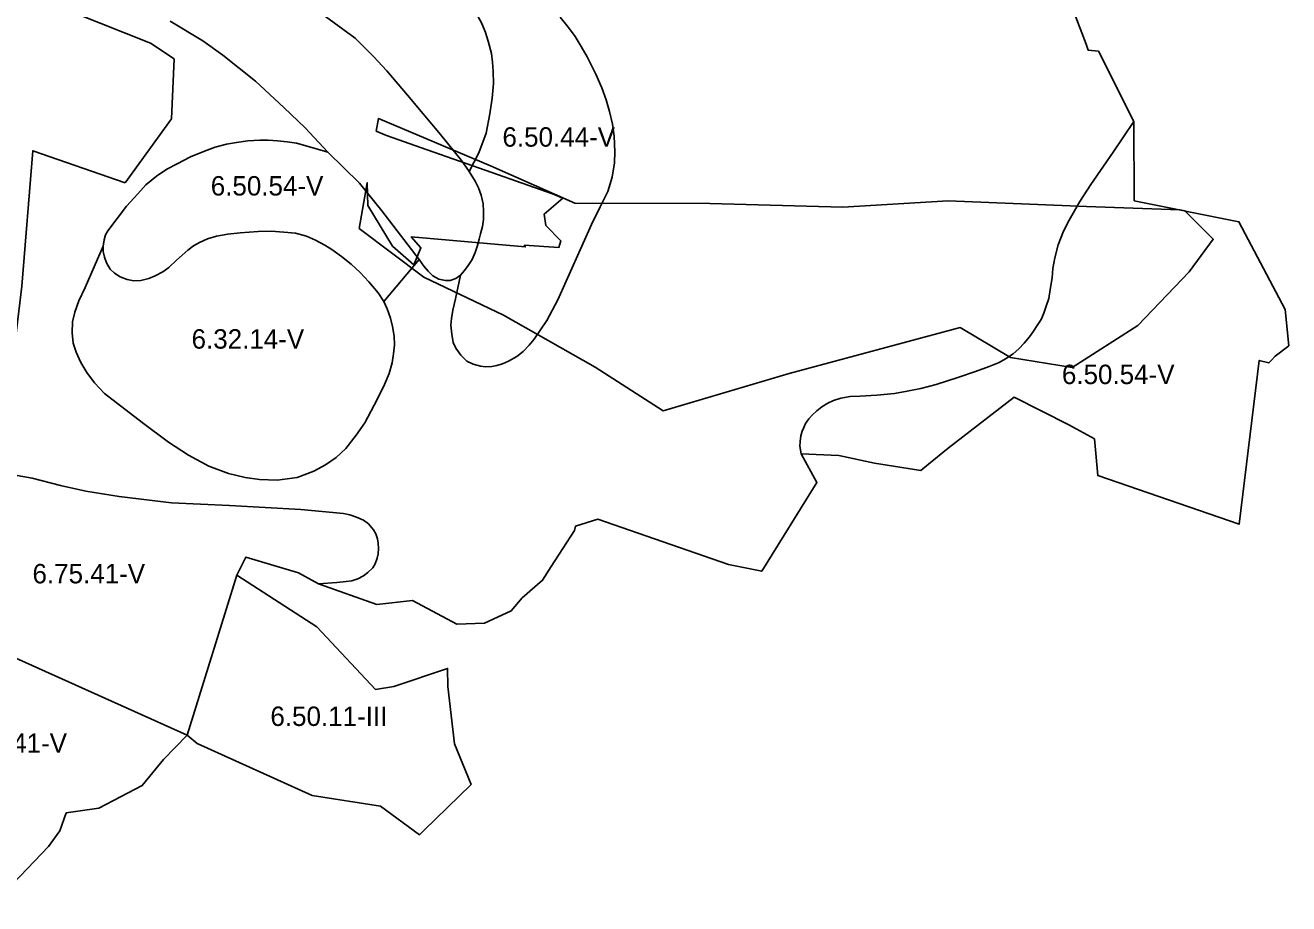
# Model space of a CAD drawing. Extents: x -555156 to -540209, y -1046851 to -1035695.
# Drawn here: x -543112 to -542461, y -1042405 to -1041952 of the extents above; entities that cross this region are included whole.
import ezdxf

# ---------------------------------------------------------------- set-up
doc = ezdxf.new("R2010")
doc.units = 0
for name, color, linetype in [('Vrstva 27', 7, 'Continuous'), ('Vrstva 28', 7, 'Continuous'), ('Vrstva 29', 7, 'Continuous')]:
    doc.layers.add(name, color=color, linetype=linetype)

msp = doc.modelspace()

# ---------------------------------------------------------------- linework, layer by layer
at = {"layer": 'Vrstva 28'}
for points in [[(-543225.96, -1041792.46), (-543222.64, -1041795.92), (-543215.38, -1041803.54), (-543208.99, -1041809.13), (-543200.39, -1041816.16), (-543189.37, -1041824.04), (-543175.69, -1041832.52), (-543154.37, -1041842.09), (-543111.98, -1041858.81), (-543067, -1041879.05), (-543042.63, -1041892.2), (-543014.86, -1041908.52), (-542980.74, -1041930.37), (-542941.96, -1041958.78), (-542932.46, -1041968.21), (-542925.68, -1041975.6), (-542915.02, -1041988.2), (-542897.95, -1042008.44), (-542887.17, -1042021.77), (-542883.23, -1042027.58)], [(-542581.52, -1041920.08), (-542565.67, -1041961.95), (-542564.48, -1041965.09), (-542559.18, -1041965.6), (-542541, -1042001.74)], [(-542883.23, -1042027.58), (-542878.31, -1042017.92), (-542874.5, -1042007.74), (-542872.68, -1041997.81), (-542871.35, -1041989.81), (-542870.74, -1041982.18), (-542870.86, -1041976), (-542871.23, -1041971.15), (-542871.85, -1041966.73), (-542873.43, -1041960.43), (-542874.88, -1041955.95), (-542876.82, -1041951.35), (-542879.6, -1041945.89), (-542882.75, -1041940.2), (-542885.9, -1041935.35), (-542892.58, -1041927.43)], [(-542956.03, -1042017.47), (-542967.69, -1042004.96), (-542978.71, -1041994.57), (-542993.33, -1041981), (-543010.07, -1041967.64), (-543020.46, -1041960.22), (-543037.2, -1041950.04)], [(-542836.49, -1041948.07), (-542832.13, -1041953.28), (-542828.62, -1041958.01), (-542825.59, -1041963.1), (-542822.44, -1041968.43), (-542818.01, -1041977.42), (-542814.99, -1041984.45), (-542812.81, -1041990.63), (-542810.99, -1041996.57), (-542809.54, -1042003.11), (-542808.69, -1042009.29), (-542808.33, -1042017.41), (-542808.45, -1042023.1), (-542809.66, -1042030.49), (-542811.84, -1042037.76), (-542815.83, -1042045.62), (-542820.28, -1042054.74), (-542837.66, -1042093.54), (-542843.2, -1042104.17), (-542849.74, -1042113.87), (-542852.3, -1042116.97), (-542855.55, -1042120.29), (-542858.8, -1042122.71), (-542863.02, -1042125.14), (-542866.07, -1042126.52), (-542869.11, -1042127.49), (-542871.67, -1042127.98), (-542874.65, -1042128.05), (-542877.42, -1042127.77), (-542881.22, -1042126.8), (-542884.41, -1042125.14), (-542887.59, -1042122.16), (-542890.22, -1042118.49), (-542891.47, -1042115.51), (-542892.23, -1042111.36), (-542892.64, -1042106.65), (-542892.43, -1042103.26), (-542891.6, -1042098.89), (-542890.36, -1042093.15), (-542887.69, -1042080.92)], [(-542712.28, -1042173.01), (-542712.98, -1042168.98), (-542712.91, -1042166.56), (-542712.57, -1042163.58), (-542711.88, -1042161.3), (-542711.04, -1042159.43), (-542710.08, -1042157.28), (-542708.42, -1042154.93), (-542706.48, -1042152.78), (-542704.26, -1042150.77), (-542701.7, -1042148.77), (-542698.66, -1042146.9), (-542695.61, -1042145.51), (-542691.88, -1042144.33), (-542687.1, -1042143.43), (-542681.98, -1042143.3), (-542673.4, -1042142.74), (-542664.33, -1042141.84), (-542657.83, -1042140.73), (-542650.63, -1042139.28), (-542642.81, -1042137.13), (-542631.67, -1042133.53), (-542622.52, -1042130.59), (-542615.46, -1042127.88), (-542610.41, -1042125.88), (-542607.15, -1042124.08), (-542603.21, -1042121.38), (-542600.23, -1042118.81), (-542597.53, -1042115.91), (-542594.76, -1042112.65), (-542592.76, -1042109.81), (-542590.75, -1042106.84), (-542588.74, -1042103.65), (-542587.43, -1042100.47), (-542586.11, -1042096.8), (-542584.87, -1042092.85), (-542584.04, -1042088.21), (-542583.14, -1042082.32), (-542582.79, -1042077.41), (-542581.78, -1042072), (-542579.97, -1042065.33), (-542577.18, -1042058.18), (-542574.28, -1042052.49), (-542568.83, -1042042.92), (-542563.25, -1042034.19), (-542551.75, -1042017.59), (-542541, -1042001.74)], [(-542541, -1042001.74), (-542540.87, -1042042.64)], [(-543071.64, -1042066), (-543071.16, -1042062.74), (-543070.47, -1042060.18), (-543069.38, -1042058.03), (-543064.46, -1042051.66), (-543059.62, -1042045.29), (-543053.88, -1042038.99), (-543049.72, -1042034.42), (-543044.33, -1042029.92), (-543038.93, -1042026.32), (-543033.67, -1042023.48), (-543026.75, -1042020), (-543019.62, -1042017.02), (-543014.08, -1042014.95), (-543008.2, -1042013.49), (-543003.15, -1042012.59), (-542997.2, -1042011.69), (-542990.97, -1042011.35), (-542986.68, -1042011.28), (-542982.04, -1042011.69)], [(-542982.04, -1042011.69), (-542977.06, -1042012.18), (-542972.22, -1042012.94), (-542967.86, -1042014.05), (-542956.03, -1042017.47)], [(-542956.03, -1042017.47), (-542939.67, -1042033.49), (-542928.25, -1042047.82), (-542908.94, -1042072.88)], [(-542887.69, -1042080.92), (-542885.69, -1042078.42), (-542883.75, -1042075.86), (-542881.81, -1042072.85), (-542880.22, -1042069.25), (-542879.04, -1042065.65), (-542878.07, -1042062.39), (-542877.38, -1042059.69), (-542876.48, -1042055.89), (-542875.93, -1042052.22), (-542875.86, -1042047.92), (-542876, -1042044.12), (-542877.11, -1042039.75), (-542878.49, -1042035.88), (-542880.2, -1042032.43), (-542883.23, -1042027.58)], [(-542540.87, -1042042.64), (-542486.91, -1042053.36), (-542463.15, -1042098.63), (-542461.29, -1042117.23), (-542468.27, -1042122.68), (-542470.16, -1042124.68), (-542470.78, -1042125.34), (-542471.52, -1042126.13), (-542476.47, -1042124.82), (-542486.86, -1042209.24), (-542559.66, -1042184.15), (-542561.3, -1042165.24), (-542574.55, -1042157.99), (-542602.69, -1042143.77), (-542636.58, -1042169.93), (-542646.72, -1042178.28), (-542650.69, -1042181.55), (-542674.6, -1042177.66), (-542692.99, -1042173.84), (-542712.28, -1042173.01)], [(-543071.64, -1042066), (-543071.64, -1042068.7), (-543071.02, -1042071.6), (-543069.98, -1042074.51), (-543068.12, -1042077.77), (-543065.9, -1042079.91), (-543062.92, -1042081.78), (-543059.33, -1042083.1), (-543055.87, -1042083.79), (-543052.34, -1042083.58), (-543048.12, -1042082.61), (-543044.86, -1042081.16), (-543041.06, -1042079.22), (-543037.87, -1042076.87), (-543034, -1042073.2), (-543028.12, -1042068.07), (-543025.14, -1042065.79), (-543022.09, -1042064.13), (-543018.08, -1042062.19), (-543013.31, -1042060.8), (-543007.56, -1042059.76), (-543001.26, -1042059.14), (-542991.99, -1042058.45), (-542985.14, -1042058.24), (-542978.63, -1042058.68)], [(-542978.63, -1042058.68), (-542972.7, -1042059.28), (-542967.01, -1042060.86), (-542962.42, -1042062.92), (-542957.58, -1042065.48), (-542953.91, -1042067.7), (-542949, -1042071.23), (-542944.02, -1042075.31), (-542939.45, -1042079.47), (-542934.88, -1042084.31), (-542930.17, -1042089.99), (-542927.27, -1042094.42)], [(-542927.27, -1042094.42), (-542925.55, -1042098.21), (-542923.82, -1042103.05), (-542922.71, -1042107.41), (-542921.81, -1042112.4), (-542921.74, -1042116.76), (-542922.22, -1042121.47), (-542922.92, -1042126.11), (-542924.44, -1042131.58), (-542926.86, -1042137.26), (-542930.6, -1042145.01), (-542937.01, -1042156.97), (-542941.49, -1042163.28), (-542946.82, -1042170.18), (-542951.78, -1042174.79), (-542957.23, -1042178.54), (-542963.17, -1042181.81), (-542971.89, -1042185.09), (-542982.06, -1042186.54), (-542991.26, -1042186.18), (-542998.65, -1042185.09), (-543007.25, -1042183.03), (-543017.3, -1042179.27), (-543027.72, -1042173.57), (-543038.13, -1042166.91), (-543051.58, -1042156.73), (-543070.95, -1042141.83), (-543076.19, -1042136.34), (-543080.19, -1042131.01), (-543083.21, -1042125.92), (-543085.64, -1042120.59), (-543087.09, -1042115.87), (-543087.7, -1042110.66), (-543087.45, -1042104.96), (-543086.36, -1042099.99), (-543084.18, -1042094.18), (-543080.91, -1042087.27), (-543071.64, -1042066)], [(-542908.94, -1042072.88), (-542927.27, -1042094.42)], [(-542887.69, -1042080.92), (-542890.19, -1042082.65), (-542893.02, -1042083.69), (-542895.45, -1042083.69), (-542898.91, -1042082.92), (-542902.02, -1042081.19), (-542904.44, -1042078.84), (-542906.59, -1042076.28), (-542908.94, -1042072.88)], [(-542712.28, -1042173.01), (-542704.2, -1042187.61), (-542732.59, -1042233.37), (-542749.67, -1042229.86), (-542796.29, -1042213.78), (-542817.07, -1042206.61), (-542828.55, -1042210.13), (-542828.96, -1042212.41), (-542841.1, -1042230.89), (-542845.49, -1042238.03), (-542856.03, -1042247.12), (-542861.64, -1042253.87), (-542875.36, -1042260.19), (-542889.56, -1042260.67), (-542912.5, -1042248.52), (-542930.87, -1042250.55), (-542960.8, -1042239.9)], [(-543134.41, -1042180.86), (-543108.33, -1042185.51), (-543093.71, -1042189.32), (-543080.57, -1042192.08), (-543063.4, -1042194.84), (-543036.49, -1042198.23), (-543006.6, -1042199.5), (-542969.94, -1042201.62), (-542947.9, -1042203.74), (-542944.73, -1042204.29), (-542941.2, -1042205.47), (-542937.74, -1042207.06), (-542935.18, -1042209.07), (-542932.55, -1042212.05), (-542931.3, -1042214.12), (-542930.4, -1042216.76), (-542930.13, -1042218.9), (-542929.92, -1042221.67), (-542930.2, -1042224.51), (-542930.68, -1042226.73), (-542931.65, -1042229.63), (-542932.89, -1042231.64), (-542935.39, -1042234.07), (-542937.6, -1042235.73), (-542940.65, -1042237.39), (-542943.76, -1042238.43), (-542946.6, -1042238.77), (-542951.44, -1042239.12), (-542960.8, -1042239.9)], [(-542960.8, -1042239.9), (-542971.12, -1042234.29), (-542998.34, -1042226.15), (-543002.98, -1042235.39)], [(-543028.48, -1042317.84), (-543040.73, -1042330.31), (-543051.61, -1042343.83), (-543073.88, -1042355.42), (-543090.71, -1042357.86), (-543094.07, -1042367.08), (-543099.86, -1042375.17), (-543125.43, -1042401.77), (-543140.44, -1042404.67), (-543165.41, -1042363.31), (-543154.81, -1042335.03), (-543169.11, -1042293.13), (-543194.16, -1042279.71), (-543207.13, -1042243.97), (-543211.97, -1042235.36)], [(-543211.97, -1042235.36), (-543028.48, -1042317.84)], [(-543028.48, -1042317.84), (-543002.98, -1042235.39)], [(-543002.98, -1042235.39), (-542961.69, -1042261.96)], [(-542961.69, -1042261.96), (-542931.44, -1042294.26), (-542922.09, -1042292.84), (-542894.38, -1042283.5), (-542894.2, -1042292.77), (-542890.88, -1042322.29), (-542882.26, -1042343.2), (-542906.61, -1042367.01), (-542908.81, -1042369.16), (-542928.9, -1042354.42), (-542964.14, -1042348.92), (-543023.31, -1042322.07), (-543028.48, -1042317.84)]]:
    msp.add_lwpolyline(points, dxfattribs=at)
at = {"layer": 'Vrstva 29'}
for points in [[(-543060.307008, -1042033.329996), (-543036.606999, -1042000.406997), (-543035.205002, -1041969.552007), (-543047.345004, -1041961.404005), (-543112.527992, -1041935.279008), (-543197.320006, -1041897.844005), (-543306.637991, -1041841.744998), (-543312.228998, -1041905.962998), (-543315.093996, -1041944.183994), (-543296.347991, -1041969.943005), (-543276.502999, -1042002.945003), (-543265.462002, -1042045.301004), (-543260.400007, -1042080.712001), (-543253.232999, -1042136.973997), (-543203.009001, -1042145.861006), (-543122.192005, -1042157.931992), (-543113.627991, -1042086.605005), (-543108.014993, -1042016.779993), (-543060.307008, -1042033.329996)], [(-542931.075946, -1042006.699886), (-542925.76, -1042008.97), (-542904.95, -1042016.26), (-542871.57, -1042027.95), (-542840.28, -1042038.92), (-542835, -1042041.25), (-542844.57, -1042049.45), (-542843.76, -1042055.34), (-542836.02, -1042063.18), (-542837.13, -1042066.71), (-542854.88, -1042065.51), (-542854.36, -1042066.32), (-542913.08, -1042061.18), (-542908.1, -1042066.8), (-542911.81, -1042075.59), (-542922.7, -1042065.95), (-542935.37, -1042045.06), (-542935.77997, -1042033.300001), (-542939.940002, -1042056.823975), (-542906.619019, -1042081.909973), (-542865.533997, -1042101.455994), (-542818.34198, -1042128.307983), (-542783.455017, -1042150.755005), (-542718.447998, -1042131.525024), (-542630.458008, -1042107.901001), (-542604.513, -1042123.242981), (-542572.862976, -1042128.479004), (-542539.051025, -1042106.872986), (-542512.494995, -1042079.112), (-542500.177979, -1042062.317993), (-542514.740745, -1042047.830986), (-542517.304294, -1042047.321697), (-542565.343994, -1042045.513), (-542636.630005, -1042042.602905), (-542690.946899, -1042045.882996), (-542759.281982, -1042044.059998), (-542828.822021, -1042043.893982), (-542872.237, -1042024.60498), (-542929.924011, -1042000.185974), (-542931.075946, -1042006.699886)]]:
    msp.add_lwpolyline(points, dxfattribs=at)

# ---------------------------------------------------------------- texts
at = {"layer": 'Vrstva 27'}
for s, p in [('6.50.44-V', (-542866.140884, -1042014.71)), ('6.50.54-V', (-543016.320884, -1042039.87)), ('6.32.14-V', (-543026.190884, -1042118.74)), ('6.50.54-V', (-542578.070884, -1042137.01)), ('6.75.41-V', (-543108.111006, -1042239.65)), ('6.50.11-III', (-542985.616548, -1042313.1)), ('6.76.41-V', (-543148.321006, -1042326.93))]:
    msp.add_text(s, height=10, dxfattribs=at).set_placement(p)

doc.saveas('drawing.dxf')
